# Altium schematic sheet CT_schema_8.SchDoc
size 287 x 160 mm
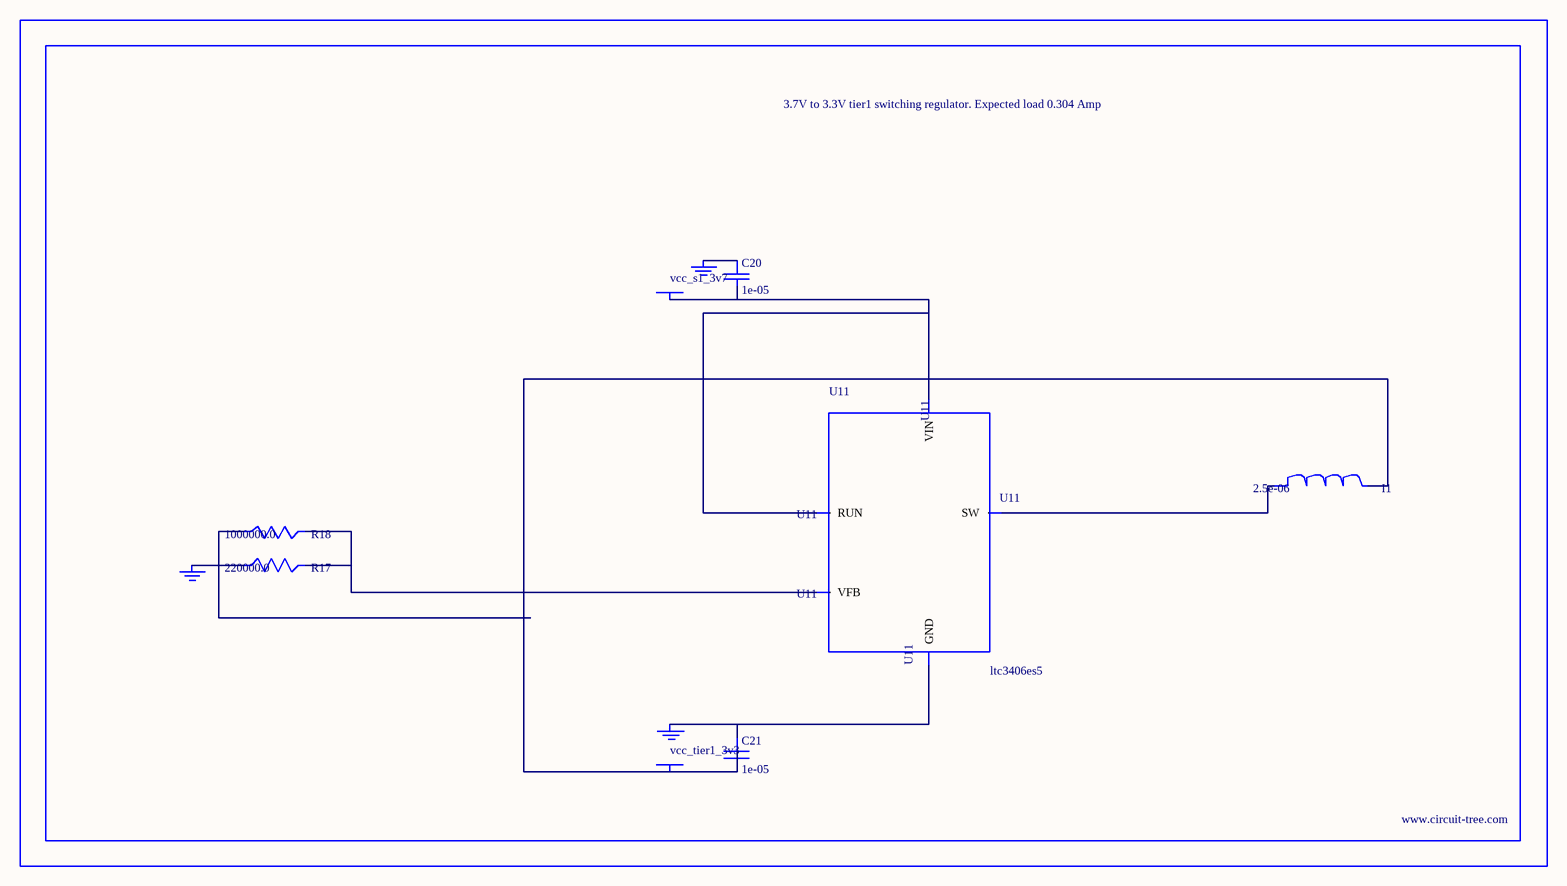
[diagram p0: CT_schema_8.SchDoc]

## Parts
BORDER7  (no value)
C20  1e-05  [C0805]
C21  1e-05  [C0805]
GND_INSTANCE_7_0  (no value)
GND_INSTANCE_7_1  (no value)
GND_INSTANCE_7_2  (no value)
I1  2.5e-06  [DR1040]
POWER_INSTANCE_7_0  vcc_tier1_3v3
POWER_INSTANCE_7_1  vcc_s1_3v7
R17  220000.0  [R0603]
R18  1000000.0  [R0603]
U11  ltc3406es5  [TSOT-23-5]

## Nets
NetC20_1: C20.1 GND_INSTANCE_7_1.0(GND)
NetC20_2: C20.2 POWER_INSTANCE_7_1.0(PWR) U11.1(RUN) U11.4(VIN)
NetC21_1: C21.1 GND_INSTANCE_7_0.0(GND) U11.2(GND)
NetC21_2: C21.2 I1.2 POWER_INSTANCE_7_0.0(PWR) R18.1
NetGND_INSTANCE_7_2_0: GND_INSTANCE_7_2.0(GND) R17.1
NetI1_1: I1.1 U11.3(SW)
NetR17_2: R17.2 R18.2 U11.5(VFB)

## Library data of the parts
BORDER7 = BORDER_PAGE7
C20 C21 = C0805C106K8RACTU
GND_INSTANCE_7_0-GND_INSTANCE_7_2 = GND
I1 = DR1040-2R5-R
POWER_INSTANCE_7_0 POWER_INSTANCE_7_1 = PWR
R17 = RC0603JR-07220KL
R18 = RC0603JR-071ML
